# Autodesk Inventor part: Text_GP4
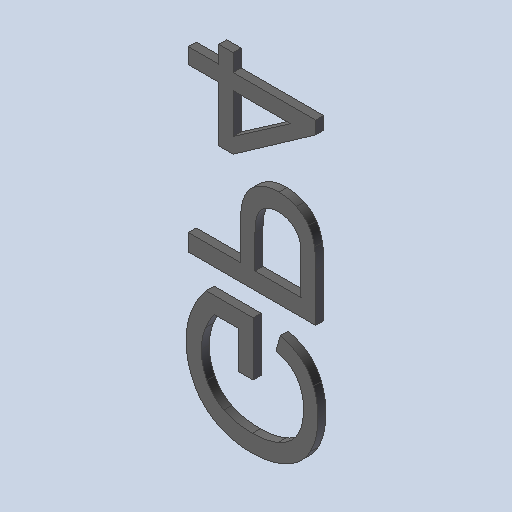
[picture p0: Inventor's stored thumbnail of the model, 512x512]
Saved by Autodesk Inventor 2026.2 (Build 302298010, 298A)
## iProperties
Created: 2026-10
Part Number: Text_GP4
Material: Générique
Document SubType Name: Modeling
Designer: mel
Density: 1 g/cm^3
Appearance: Par défaut
Author: mel
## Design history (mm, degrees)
feature "Base1"
feature "Base2"
feature "Base3"
node "Solide1"
node "Solide2"
node "Solide3"
